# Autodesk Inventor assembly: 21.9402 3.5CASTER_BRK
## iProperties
Created: 2010-10
Part Number: 21.9402 3.5CASTER_BRK
Document SubType Name: Assembly
Designer: Administrator
Translation Standard: STEP AP214IS
FileName: Colson-2.03256.445 BRK5 .step.step
PreProcessor: SolidWorks 2010
PostProcessor: Build: 236a, Release: 2009 RTM - Date: Fri 02/22/2008
Sent Units: Inches
Uncertainty: 1e-05
Author: Administrator
